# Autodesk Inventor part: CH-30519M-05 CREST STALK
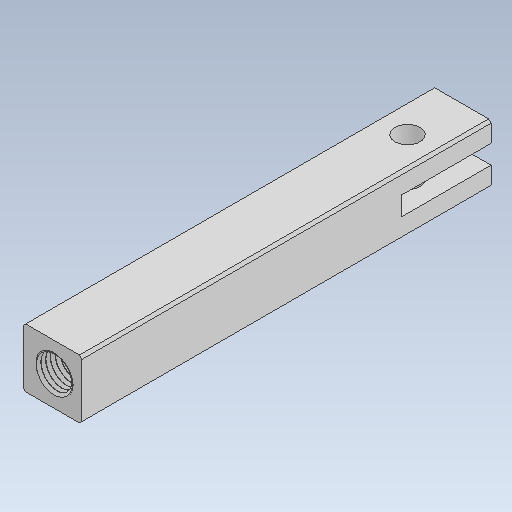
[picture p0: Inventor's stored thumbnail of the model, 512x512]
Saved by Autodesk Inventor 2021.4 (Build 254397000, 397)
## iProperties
Created: 2017-11
Part Number: CH-30519M-05 CREST STALK
Material: Ogólny
Document SubType Name: Modeling
Designer: user
Density: 1 g/cm^3
Appearance: Domyślna
Author: user
Revision Number: ÈÎºÎ
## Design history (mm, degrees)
feature "ÇÐ³ý-É¨Ãè2"
node "Bryła1"
